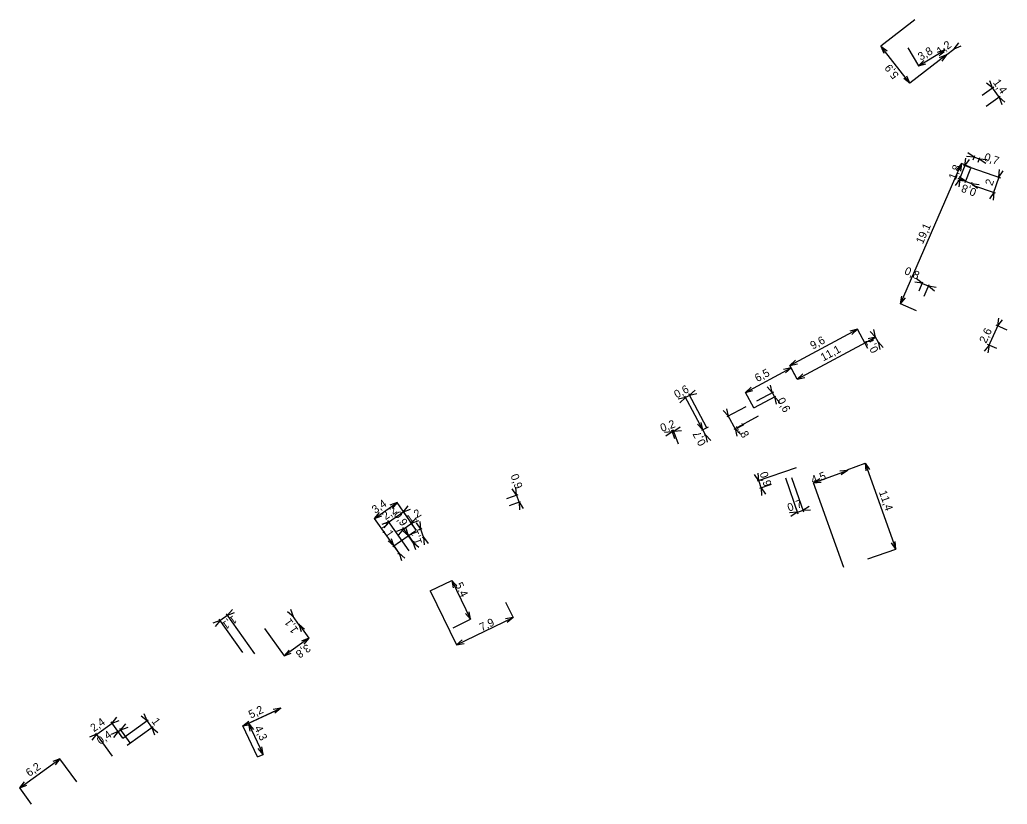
# Model space of a CAD drawing. Extents: x -743919 to -743796, y -1055885 to -1055787.
import ezdxf

# ---------------------------------------------------------------- set-up
doc = ezdxf.new("R2010")
doc.units = 0
doc.layers.add('Kota_NN', color=7, linetype='Continuous')
doc.layers.add('Kota_VN', color=7, linetype='Continuous')

msp = doc.modelspace()

# ---------------------------------------------------------------- linework, layer by layer
at = {"layer": 'Kota_NN'}
for p, q in [((-743807.98, -1055791), (-743806.63, -1055793.25)), ((-743806.63, -1055793.25), (-743803.38, -1055791.3)), ((-743803.38, -1055791.3), (-743804.31, -1055791.57)), ((-743803.38, -1055791.3), (-743804.05, -1055791.99)), ((-743803.51, -1055791.09), (-743803.38, -1055791.3)), ((-743806.63, -1055793.25), (-743805.96, -1055792.56)), ((-743806.63, -1055793.25), (-743805.71, -1055792.98)), ((-743798.69, -1055796.92), (-743797.23, -1055795.88)), ((-743797.4, -1055796), (-743798.14, -1055795.39)), ((-743797.4, -1055796), (-743797.73, -1055795.1)), ((-743797.51, -1055795.84), (-743796.46, -1055797.31)), ((-743798.18, -1055798.29), (-743796.42, -1055797.03)), ((-743796.58, -1055797.15), (-743795.84, -1055797.76)), ((-743796.58, -1055797.15), (-743796.24, -1055798.05)), ((-743799.68, -1055804.65), (-743800.64, -1055804.58)), ((-743799.68, -1055804.65), (-743800.48, -1055804.11)), ((-743799.87, -1055804.58), (-743798.85, -1055804.93)), ((-743799.8, -1055805), (-743799.61, -1055804.46)), ((-743808.88, -1055822.97), (-743801.27, -1055805.45)), ((-743801.27, -1055805.45), (-743801.86, -1055806.2)), ((-743801.27, -1055805.45), (-743801.41, -1055806.4)), ((-743800.12, -1055805.95), (-743801.27, -1055805.45)), ((-743799.18, -1055805.27), (-743798.98, -1055804.68)), ((-743799.04, -1055804.86), (-743798.08, -1055804.93)), ((-743799.04, -1055804.86), (-743798.24, -1055805.4)), ((-743800.12, -1055805.95), (-743796.41, -1055807.21)), ((-743797.31, -1055809.25), (-743796.53, -1055806.96)), ((-743796.59, -1055807.15), (-743796.53, -1055806.19)), ((-743796.59, -1055807.15), (-743796.06, -1055806.35)), ((-743799.89, -1055808.16), (-743797.06, -1055809.12)), ((-743797.24, -1055809.06), (-743797.78, -1055809.86)), ((-743797.24, -1055809.06), (-743797.31, -1055810.02)), ((-743806.17, -1055820.41), (-743807.11, -1055820.26)), ((-743806.17, -1055820.41), (-743806.92, -1055819.81)), ((-743806.57, -1055821.34), (-743806.09, -1055820.22)), ((-743806.35, -1055820.33), (-743805.21, -1055820.82)), ((-743805.95, -1055822.02), (-743805.31, -1055820.56)), ((-743805.39, -1055820.74), (-743804.44, -1055820.88)), ((-743805.39, -1055820.74), (-743804.64, -1055821.34)), ((-743808.88, -1055822.97), (-743808.74, -1055822.02)), ((-743808.88, -1055822.97), (-743808.28, -1055822.22)), ((-743806.9, -1055823.83), (-743808.88, -1055822.97)), ((-743797.9, -1055828.32), (-743796.66, -1055825.54)), ((-743796.74, -1055825.72), (-743796.59, -1055824.77)), ((-743796.74, -1055825.72), (-743796.13, -1055824.97)), ((-743822.7, -1055830.69), (-743814.27, -1055826.15)), ((-743814.27, -1055826.15), (-743815.21, -1055826.37)), ((-743814.27, -1055826.15), (-743814.97, -1055826.81)), ((-743812.98, -1055828.56), (-743814.27, -1055826.15)), ((-743795.55, -1055826.25), (-743796.92, -1055825.64)), ((-743796.85, -1055828.57), (-743798, -1055828.05)), ((-743797.82, -1055828.14), (-743798.43, -1055828.88)), ((-743797.82, -1055828.14), (-743797.97, -1055829.09)), ((-743822.7, -1055830.69), (-743822, -1055830.03)), ((-743822.7, -1055830.69), (-743821.77, -1055830.46)), ((-743828.27, -1055834.03), (-743822.56, -1055830.95)), ((-743822.56, -1055830.95), (-743823.49, -1055831.17)), ((-743822.56, -1055830.95), (-743823.26, -1055831.61)), ((-743821.79, -1055832.38), (-743822.7, -1055830.69)), ((-743821.79, -1055832.38), (-743822.56, -1055830.95)), ((-743828.27, -1055834.03), (-743827.57, -1055833.37)), ((-743828.27, -1055834.03), (-743827.33, -1055833.81)), ((-743827.22, -1055835.98), (-743828.27, -1055834.03)), ((-743826.86, -1055835.11), (-743824.73, -1055833.96)), ((-743824.91, -1055834.06), (-743825.57, -1055833.36)), ((-743824.91, -1055834.06), (-743825.13, -1055833.12)), ((-743825.01, -1055833.88), (-743824.53, -1055834.76)), ((-743827.22, -1055835.98), (-743824.45, -1055834.49)), ((-743824.63, -1055834.59), (-743823.97, -1055835.29)), ((-743824.63, -1055834.59), (-743824.41, -1055835.52)), ((-743830.39, -1055837.01), (-743831.05, -1055836.31)), ((-743830.39, -1055837.01), (-743830.61, -1055836.07)), ((-743828.21, -1055835.83), (-743830.57, -1055837.1)), ((-743830.49, -1055836.83), (-743829.46, -1055838.74)), ((-743826.67, -1055837.01), (-743829.73, -1055838.66)), ((-743837.41, -1055838.96), (-743838.37, -1055839.03)), ((-743837.41, -1055838.96), (-743838.21, -1055839.5)), ((-743837.6, -1055839.02), (-743837.02, -1055838.82)), ((-743837.1, -1055839.84), (-743837.48, -1055838.77)), ((-743836.63, -1055840.52), (-743837.28, -1055838.7)), ((-743837.21, -1055838.88), (-743836.42, -1055838.34)), ((-743837.21, -1055838.88), (-743836.25, -1055838.81)), ((-743829.56, -1055838.56), (-743828.9, -1055839.26)), ((-743829.56, -1055838.56), (-743829.34, -1055839.5)), ((-743815.55, -1055843.69), (-743813.31, -1055842.89)), ((-743813.31, -1055842.89), (-743809.48, -1055853.61)), ((-743813.31, -1055842.89), (-743812.76, -1055843.68)), ((-743813.31, -1055842.89), (-743813.23, -1055843.85)), ((-743821.94, -1055843.47), (-743826.8, -1055845.14)), ((-743826.61, -1055845.08), (-743826.68, -1055844.12)), ((-743819.76, -1055845.32), (-743815.51, -1055843.81)), ((-743815.51, -1055843.81), (-743816.47, -1055843.89)), ((-743815.51, -1055843.81), (-743816.3, -1055844.35)), ((-743815.55, -1055843.69), (-743815.51, -1055843.81)), ((-743826.61, -1055845.08), (-743827.15, -1055844.28)), ((-743826.68, -1055844.89), (-743826.24, -1055846.16)), ((-743823.27, -1055844.73), (-743821.73, -1055849.2)), ((-743822.51, -1055844.66), (-743821.03, -1055848.96)), ((-743819.76, -1055845.32), (-743818.97, -1055844.78)), ((-743819.76, -1055845.32), (-743818.8, -1055845.25)), ((-743815.97, -1055855.93), (-743819.76, -1055845.32)), ((-743856.87, -1055846.87), (-743857.42, -1055846.07)), ((-743856.87, -1055846.87), (-743856.95, -1055845.91)), ((-743825.04, -1055845.53), (-743826.49, -1055846.03)), ((-743826.31, -1055845.97), (-743825.77, -1055846.76)), ((-743826.31, -1055845.97), (-743826.24, -1055846.93)), ((-743874.61, -1055849.77), (-743871.8, -1055847.8)), ((-743871.8, -1055847.8), (-743872.7, -1055848.13)), ((-743871.8, -1055847.8), (-743872.42, -1055848.54)), ((-743869.35, -1055851.3), (-743871.8, -1055847.8)), ((-743858.08, -1055847.3), (-743856.68, -1055846.8)), ((-743857.75, -1055848.17), (-743856.37, -1055847.68)), ((-743856.94, -1055846.68), (-743856.49, -1055847.93)), ((-743856.56, -1055847.75), (-743856.02, -1055848.54)), ((-743856.56, -1055847.75), (-743856.48, -1055848.7)), ((-743874.61, -1055849.77), (-743873.99, -1055849.04)), ((-743872.98, -1055850.32), (-743870.84, -1055848.82)), ((-743869.35, -1055851.3), (-743871.12, -1055848.77)), ((-743871.01, -1055848.94), (-743870.39, -1055848.2)), ((-743871.01, -1055848.94), (-743870.1, -1055848.61)), ((-743821.8, -1055849.01), (-743822.75, -1055849.08)), ((-743821.8, -1055849.01), (-743822.59, -1055849.55)), ((-743821.98, -1055849.07), (-743820.91, -1055848.7)), ((-743821.09, -1055848.77), (-743820.3, -1055848.23)), ((-743821.09, -1055848.77), (-743820.14, -1055848.7)), ((-743874.61, -1055849.77), (-743873.71, -1055849.44)), ((-743871.55, -1055854.14), (-743874.61, -1055849.77)), ((-743872.82, -1055850.21), (-743873.72, -1055850.54)), ((-743872.82, -1055850.21), (-743873.44, -1055850.95)), ((-743870.27, -1055853.85), (-743872.94, -1055850.05)), ((-743871.14, -1055851.2), (-743869.82, -1055850.28)), ((-743869.35, -1055851.3), (-743870.1, -1055850.23)), ((-743869.99, -1055850.39), (-743869.37, -1055849.66)), ((-743869.99, -1055850.39), (-743869.08, -1055850.06)), ((-743869.44, -1055851.34), (-743872.34, -1055853.33)), ((-743870.98, -1055851.09), (-743871.88, -1055851.42)), ((-743870.98, -1055851.09), (-743871.6, -1055851.82)), ((-743869.82, -1055852.74), (-743871.09, -1055850.92)), ((-743870.35, -1055851.97), (-743871.08, -1055851.34)), ((-743870.35, -1055851.97), (-743870.67, -1055851.06)), ((-743869.44, -1055851.34), (-743870.52, -1055852.08)), ((-743872.18, -1055853.22), (-743872.91, -1055852.6)), ((-743872.18, -1055853.22), (-743872.5, -1055852.32)), ((-743870.46, -1055851.8), (-743869.71, -1055852.91)), ((-743869.82, -1055852.74), (-743869.66, -1055852.63)), ((-743869.82, -1055852.74), (-743869.09, -1055853.36)), ((-743869.82, -1055852.74), (-743869.5, -1055853.65)), ((-743809.48, -1055853.61), (-743809.56, -1055852.65)), ((-743872.29, -1055853.06), (-743871.44, -1055854.3)), ((-743812.96, -1055854.85), (-743809.48, -1055853.61)), ((-743809.48, -1055853.61), (-743810.03, -1055852.82)), ((-743871.55, -1055854.14), (-743871.71, -1055854.25)), ((-743871.55, -1055854.14), (-743870.82, -1055854.76)), ((-743871.55, -1055854.14), (-743871.23, -1055855.05)), ((-743867.66, -1055858.83), (-743864.97, -1055857.52)), ((-743864.97, -1055857.52), (-743862.61, -1055862.38)), ((-743864.97, -1055857.52), (-743864.34, -1055858.25)), ((-743864.97, -1055857.52), (-743864.79, -1055858.47)), ((-743867.66, -1055858.83), (-743864.37, -1055865.59)), ((-743858.23, -1055860.25), (-743857.3, -1055862.16)), ((-743864.8, -1055863.44), (-743862.61, -1055862.38)), ((-743864.37, -1055865.59), (-743857.3, -1055862.16)), ((-743862.61, -1055862.38), (-743863.24, -1055861.65)), ((-743862.61, -1055862.38), (-743862.79, -1055861.44)), ((-743857.3, -1055862.16), (-743858.25, -1055862.34)), ((-743857.3, -1055862.16), (-743858.03, -1055862.79)), ((-743864.37, -1055865.59), (-743863.65, -1055864.96)), ((-743864.37, -1055865.59), (-743863.43, -1055865.41)), ((-743891.06, -1055875.71), (-743886.34, -1055873.49)), ((-743886.33, -1055873.51), (-743890.36, -1055875.41)), ((-743886.34, -1055873.49), (-743887.29, -1055873.66)), ((-743886.34, -1055873.49), (-743887.08, -1055874.11)), ((-743886.33, -1055873.51), (-743886.34, -1055873.49)), ((-743907.41, -1055875.36), (-743906.81, -1055874.62)), ((-743906.06, -1055877.23), (-743902.88, -1055874.96)), ((-743903.04, -1055875.08), (-743903.78, -1055874.47)), ((-743903.04, -1055875.08), (-743903.38, -1055874.18)), ((-743903.16, -1055874.92), (-743902.34, -1055876.07)), ((-743909.5, -1055876.87), (-743907.25, -1055875.25)), ((-743906.06, -1055877.23), (-743907.53, -1055875.2)), ((-743907.41, -1055875.36), (-743906.51, -1055875.02)), ((-743906.8, -1055876.53), (-743906.14, -1055876.06)), ((-743905.14, -1055877.81), (-743906.42, -1055876.02)), ((-743906.3, -1055876.18), (-743905.69, -1055875.44)), ((-743906.3, -1055876.18), (-743905.4, -1055875.84)), ((-743905.52, -1055878.1), (-743902.29, -1055875.79)), ((-743902.45, -1055875.91), (-743901.71, -1055876.52)), ((-743902.45, -1055875.91), (-743902.12, -1055876.81)), ((-743891.06, -1055875.71), (-743890.32, -1055875.09)), ((-743891.06, -1055875.71), (-743890.11, -1055875.54)), ((-743889.23, -1055879.58), (-743891.06, -1055875.71)), ((-743890.36, -1055875.41), (-743888.54, -1055879.26)), ((-743890.36, -1055875.41), (-743889.74, -1055876.14)), ((-743890.36, -1055875.41), (-743890.19, -1055876.35)), ((-743909.34, -1055876.75), (-743910.23, -1055877.1)), ((-743909.34, -1055876.75), (-743909.94, -1055877.5)), ((-743907.37, -1055879.47), (-743909.45, -1055876.59)), ((-743906.64, -1055876.42), (-743907.54, -1055876.76)), ((-743906.64, -1055876.42), (-743907.25, -1055877.16)), ((-743906.06, -1055877.23), (-743906.75, -1055876.26)), ((-743888.54, -1055879.26), (-743889.16, -1055878.52)), ((-743888.54, -1055879.26), (-743888.71, -1055878.31)), ((-743918.95, -1055883.45), (-743913.92, -1055879.81)), ((-743913.92, -1055879.81), (-743914.81, -1055880.16)), ((-743913.92, -1055879.81), (-743914.52, -1055880.56)), ((-743911.82, -1055882.71), (-743913.92, -1055879.81)), ((-743889.23, -1055879.58), (-743888.54, -1055879.26)), ((-743918.95, -1055883.45), (-743918.34, -1055882.71)), ((-743918.95, -1055883.45), (-743918.05, -1055883.11)), ((-743917.47, -1055885.49), (-743918.95, -1055883.45))]:
    msp.add_line(p, q, dxfattribs=at)
at = {"layer": 'Kota_VN'}
for p, q in [((-743807.11, -1055787.48), (-743811.34, -1055790.77)), ((-743807.72, -1055795.42), (-743811.34, -1055790.77)), ((-743811.34, -1055790.77), (-743810.57, -1055791.35)), ((-743811.34, -1055790.77), (-743810.96, -1055791.65)), ((-743803.31, -1055791.99), (-743802.02, -1055790.99)), ((-743802.18, -1055791.12), (-743801.6, -1055790.35)), ((-743802.18, -1055791.12), (-743801.3, -1055790.74)), ((-743803.15, -1055791.87), (-743807.72, -1055795.42)), ((-743803.15, -1055791.87), (-743804.04, -1055792.24)), ((-743803.15, -1055791.87), (-743803.73, -1055792.64)), ((-743803.15, -1055791.87), (-743803.15, -1055791.87)), ((-743802.18, -1055791.12), (-743802.18, -1055791.12)), ((-743807.72, -1055795.42), (-743808.09, -1055794.54)), ((-743807.72, -1055795.42), (-743808.48, -1055794.84)), ((-743801.56, -1055807.58), (-743800.77, -1055805.53)), ((-743800.13, -1055805.99), (-743801.02, -1055805.64)), ((-743800.84, -1055805.71), (-743800.73, -1055804.76)), ((-743800.84, -1055805.71), (-743800.27, -1055804.94)), ((-743800.78, -1055807.66), (-743801.55, -1055807.09)), ((-743800.15, -1055806.06), (-743800.85, -1055807.84)), ((-743801.49, -1055807.39), (-743802.06, -1055808.17)), ((-743800.78, -1055807.66), (-743801.73, -1055807.55)), ((-743800.03, -1055807.96), (-743801.68, -1055807.32)), ((-743801.49, -1055807.39), (-743801.59, -1055808.35)), ((-743799.84, -1055808.02), (-743800.96, -1055807.59)), ((-743800.03, -1055807.96), (-743799.95, -1055807.76)), ((-743800.03, -1055807.95), (-743799.07, -1055808.06)), ((-743800.03, -1055807.95), (-743799.25, -1055808.52)), ((-743812.02, -1055827.13), (-743812.68, -1055826.43)), ((-743812.02, -1055827.13), (-743812.24, -1055826.19)), ((-743821.79, -1055832.38), (-743812.02, -1055827.13)), ((-743812.02, -1055827.13), (-743812.95, -1055827.35)), ((-743812.02, -1055827.13), (-743812.72, -1055827.78)), ((-743811.6, -1055827.9), (-743812.11, -1055826.95)), ((-743812.02, -1055827.13), (-743812.02, -1055827.13)), ((-743812.02, -1055827.13), (-743812.02, -1055827.13)), ((-743811.7, -1055827.72), (-743811.7, -1055827.72)), ((-743811.7, -1055827.72), (-743811.04, -1055828.42)), ((-743811.7, -1055827.72), (-743811.48, -1055828.66)), ((-743821.79, -1055832.38), (-743821.09, -1055831.72)), ((-743821.79, -1055832.38), (-743820.85, -1055832.16)), ((-743821.79, -1055832.38), (-743821.79, -1055832.38)), ((-743833.08, -1055838.45), (-743835.35, -1055834.22)), ((-743835.26, -1055834.4), (-743834.56, -1055833.74)), ((-743835.26, -1055834.4), (-743834.32, -1055834.18)), ((-743835.75, -1055834.66), (-743836.68, -1055834.88)), ((-743835.75, -1055834.66), (-743836.45, -1055835.32)), ((-743835.93, -1055834.76), (-743835.08, -1055834.3)), ((-743833.24, -1055839.33), (-743835.84, -1055834.49)), ((-743833.59, -1055838.72), (-743833.81, -1055837.78)), ((-743833.59, -1055838.72), (-743834.25, -1055838.02)), ((-743832.94, -1055838.37), (-743833.77, -1055838.81)), ((-743833.16, -1055839.51), (-743833.68, -1055838.54)), ((-743833.24, -1055839.33), (-743833.43, -1055839.43)), ((-743833.26, -1055839.34), (-743832.6, -1055840.04)), ((-743833.26, -1055839.34), (-743833.04, -1055840.27)), ((-743868.84, -1055851.12), (-743868.92, -1055850.16)), ((-743868.84, -1055851.12), (-743869.38, -1055850.33)), ((-743869.13, -1055851.22), (-743868.65, -1055851.05)), ((-743868.41, -1055852.32), (-743868.91, -1055850.93)), ((-743868.47, -1055852.13), (-743868.67, -1055852.2)), ((-743868.48, -1055852.13), (-743867.93, -1055852.92)), ((-743868.48, -1055852.13), (-743868.4, -1055853.09)), ((-743892.99, -1055861.88), (-743892.38, -1055861.14)), ((-743884.73, -1055862.07), (-743885.06, -1055861.17)), ((-743893.91, -1055862.54), (-743894.81, -1055862.87)), ((-743893.91, -1055862.54), (-743894.52, -1055863.28)), ((-743892.83, -1055861.77), (-743894.07, -1055862.65)), ((-743891.06, -1055866.53), (-743894.02, -1055862.37)), ((-743889.57, -1055866.68), (-743893.11, -1055861.72)), ((-743892.99, -1055861.88), (-743892.09, -1055861.55)), ((-743884.73, -1055862.07), (-743885.47, -1055861.46)), ((-743883.97, -1055863.15), (-743884.85, -1055861.91)), ((-743884.73, -1055862.07), (-743884.73, -1055862.07)), ((-743888.35, -1055863.54), (-743885.91, -1055866.96)), ((-743884.09, -1055862.99), (-743884.09, -1055862.99)), ((-743884.09, -1055862.99), (-743883.35, -1055863.61)), ((-743884.09, -1055862.99), (-743883.76, -1055863.89)), ((-743884.09, -1055862.99), (-743882.82, -1055864.76)), ((-743882.82, -1055864.76), (-743885.91, -1055866.96)), ((-743882.82, -1055864.76), (-743883.72, -1055865.1)), ((-743882.82, -1055864.76), (-743883.43, -1055865.5)), ((-743885.91, -1055866.96), (-743885.29, -1055866.22)), ((-743885.91, -1055866.96), (-743885.01, -1055866.63))]:
    msp.add_line(p, q, dxfattribs=at)

# ---------------------------------------------------------------- texts
at = {"layer": 'Kota_NN'}
for s, rotation, p in [('3,8', 30.8811, (-743806.35, -1055792.61)), ('1,4', 305.4761, (-743797.38, -1055795.33)), ('0,7', 341.2094, (-743798.53, -1055805.03)), ('2', 71.2106, (-743797.41, -1055808.29)), ('19,1', 66.4961, (-743806.1, -1055815.57)), ('0,8', 336.4952, (-743808.49, -1055819.21)), ('2,6', 65.9395, (-743798.19, -1055827.98)), ('9,6', 28.2659, (-743819.85, -1055828.7)), ('6,5', 28.2654, (-743826.77, -1055832.77)), ('0,6', 298.2651, (-743824.34, -1055835.01)), ('0,2', 19.5622, (-743838.7, -1055838.99)), ('1,8', 298.2653, (-743829.5, -1055838.19)), ('0,9', 289.0123, (-743826.51, -1055844.14)), ('4,5', 19.645, (-743819.86, -1055845.47)), ('0,9', 289.5624, (-743857.63, -1055844.43)), ('11,4', 289.6455, (-743811.6, -1055846.48)), ('3,4', 35.013, (-743874.52, -1055849.22)), ('0,7', 19.0121, (-743822.83, -1055848.94)), ('2,2', 35.0134, (-743873.23, -1055850.01)), ('0,9', 304.4715, (-743872.26, -1055849.31)), ('1,2', 35.0116, (-743870.2, -1055850.41)), ('1,1', 304.4704, (-743873.99, -1055850.73)), ('5,4', 295.9229, (-743864.58, -1055858.05)), ('7,9', 25.923, (-743861.21, -1055863.9)), ('5,2', 25.2448, (-743890.07, -1055874.8)), ('2,4', 35.9017, (-743909.68, -1055876.51)), ('1', 305.5019, (-743902.52, -1055875.13)), ('4,3', 295.2447, (-743889.65, -1055875.96)), ('0,4', 35.5015, (-743908.88, -1055878.09)), ('6,2', 35.9018, (-743917.74, -1055882.09))]:
    msp.add_text(s, height=1, rotation=rotation, dxfattribs=at).set_placement(p)
at = {"layer": 'Kota_VN'}
for s, rotation, p in [('1,2', 37.8801, (-743803.89, -1055791.94)), ('5,9', 127.8801, (-743809.03, -1055794.39)), ('1,8', 68.763, (-743801.99, -1055807.56)), ('0,8', 158.7302, (-743799.31, -1055808.66)), ('0,7', 118.2655, (-743811.58, -1055828.78)), ('11,1', 28.2653, (-743818.55, -1055830.18)), ('0,6', 28.2653, (-743836.86, -1055834.81)), ('0,7', 118.2442, (-743833.15, -1055840.39)), ('1,1', 109.5783, (-743868.65, -1055852.85)), ('1,1', 215.5022, (-743892.28, -1055861.86)), ('1,1', 125.0129, (-743884.07, -1055863.71)), ('3,8', 215.5379, (-743883.05, -1055865.42))]:
    msp.add_text(s, height=1, rotation=rotation, dxfattribs=at).set_placement(p)

doc.saveas('drawing.dxf')
